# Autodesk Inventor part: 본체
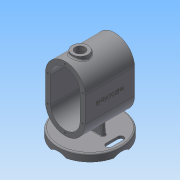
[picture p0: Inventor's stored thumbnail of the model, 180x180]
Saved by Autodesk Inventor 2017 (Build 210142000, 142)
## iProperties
Created: 2016-12
Part Number: 본체
Material: 알루미늄 6061
Document SubType Name: Modeling
Designer: mduedu
Density: 2.71 g/cm^3
Appearance: 기본값
Mass: 1098.85 g
Surface Area: 1080.89 cm^2
Volume: 405.481 cm^3
Author: mduedu
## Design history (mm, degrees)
sketch "스케치1"
  geometry: L1 (40, -25)-(40, 25); L2 (-40, 25)-(-40, -25); L3 (-40, -25)-(40, 25); L4 (40, -25)-(-40, 25); L5 (0, 25)-(0, -25); A1 r 40 centre (0, 25) between (40, 25) and (-40, 25); A2 r 40 centre (0, -25) between (-40, -25) and (40, -25); 1 further point
  constraints: 10 end point, 4 point on circle, 3 tangent, 2 centre point, 2 midpoint, 2 parallel, 1 vertical
  dimensions: "d0" = 130 dimension on A2 A1; "d2" = 80 distance between parallel lines of L1 L2
extrude "돌출1" new body sketch "스케치1" stored distance "d3" = 100; taper "d4" = 0 deg
feature "쉘1" dims "d5" = 10
sketch "스케치2"
  geometry: L1 (-75, 65)-(-90, 65); L2 (-90, 65)-(-90, 0); L3 (-75, 0)-(-75, 65); L4 (-75, 0)-(-90, 0); 1 further point
  constraints: 8 end point, 1 horizontal, 1 horizontal alignment, 1 parallel, 1 perpendicular
  dimensions: "d6" = 90 distance from line of L2 point (0, 0); "d83" = 15 distance of L1.start L1.end; "d84" = 130 diameter of L1 L4
revolve "회전1" sketch "스케치2" stored, may be unused: angle "d85" = 90 deg
fillet "모깎기5" dims "d86" = 3
hole "구멍6" diameter "d89" = 120; stored, may be unused: countersink angle "d93" = 90 deg, drill point angle "d95" = 0 deg; dims "d87" = 10, "d88" = 10, "d90" = 6, "d91" = 4, "d92" = 2, "d94" = 10
sketch "스케치15"
  geometry: L1 (-90, -60)-(-90, 60) reference; A1 r 21.75 centre (-105.75, 0) between (-90, -15) and (-90, 15); 3 further points
  constraints: 3 point on circle, 2 point on line, 1 centre point, 1 horizontal alignment, 1 midpoint
  dimensions: "d119" = 30 distance of A1.start A1.end; "d120" = 6 distance of point (-84, 0) point (-90, 0)
extrude "돌출6" cut sketch "스케치15" stored distance "d97" = 10; taper "d98" = 0 deg
sketch "스케치5"
  geometry: L1 (4, -30)-(-4, -30); L2 (-4, -30)-(-4, 30); L3 (-4, 30)-(4, 30); L4 (4, 30)-(4, -30); L5 (4, -30)-(-4, 30); L6 (-4, -30)-(4, 30); 3 further points
  constraints: 12 end point, 3 midpoint, 2 parallel, 1 coincident, 1 horizontal, 1 perpendicular
  dimensions: "d22" = 8 distance of L2.end L3.end; "d24" = 60 distance of L1.end L2.end
extrude "돌출3" join sketch "스케치5" stored distance "d25" = 80; taper "d26" = 0 deg
feature "면 기울기1" dims angle "d27" = 5 deg
sketch "스케치6"
  geometry: L1 (-28.115, -53.453)-(-30, -75); L2 (-62, -75)-(62, -75) reference; A1 r 40 centre (0, -25) between (-40, -25) and (40, -25) reference; 1 further point
  constraints: 2 end point, 1 point on circle, 1 point on line
  dimensions: "d28" = 30 horizontal distance of A1.centre L1.end; "d102" = 85 deg angle of L2 L1
feature "리브1" sketch "스케치6" dims "d30" = 1, "d31" = 8, "d32" = 0, "d33" = 0, "d34" = 1, "d35" = 1
fillet "모깎기2" dims "d36" = 3
fillet "모깎기3" dims "d37" = 1, "d38" = 1
node "작업 평면1"
sketch "스케치9"
  geometry: 1 further point
sketch "스케치7"
  geometry: L1 (40, 50)-(-40, 50) reference; C1 r 16 at (0, 20); 1 further point
  constraints: 1 centre point, 1 vertical alignment
  dimensions: "d40" = 32 diameter of C1; "d41" = 30 distance from line of C1.centre L1
extrude "돌출4" join sketch "스케치7" stored distance "d42" = 80; taper "d43" = 0 deg
hole "구멍2" diameter "d46" = 20; stored, may be unused: countersink angle "d50" = 90 deg, drill point angle "d52" = 118 deg; dims "d44" = 10, "d45" = 10, "d47" = 6, "d48" = 4, "d49" = 2, "d51" = 8
fillet "모깎기4" dims "d53" = 3
node "작업 평면2"
sketch "스케치8"
  geometry: C1 r 16 at (0, 0) reference; C2 r 15 at (0, 0); 1 further point
  constraints: 1 centre point, 1 coincident
  dimensions: "d55" = 30 diameter of C2
extrude "돌출5" cut sketch "스케치8" stored distance "d56" = 80; taper "d57" = 0 deg
chamfer "모따기1" distance "d58" = 1; stored, may be unused: second distance "d59" = 2, angle "d60" = 45 deg
sketch "스케치10"
  geometry: 2 further points
  constraints: 1 coincident, 1 other
feature "엠보싱1" sketch "스케치10" dims "d0" = 130, "d2" = 80, "d61" = 0.5, "d62" = 0
sketch "스케치11"
  geometry: 1 further point
hole "구멍3" sketch "스케치11" at (0, 60) diameter "d63" = 3.242; stored, may be unused: countersink angle "d67" = 90 deg, drill point angle "d69" = 120 deg; dims "d64" = 8.6, "d65" = 4, "d66" = 2, "d68" = 10.6
sketch "스케치12"
  geometry: 1 further point
hole "구멍5" sketch "스케치12" at (0, 60) diameter "d70" = 3.242; stored, may be unused: countersink angle "d74" = 90 deg, drill point angle "d76" = 120 deg; dims "d71" = 8.6, "d72" = 4, "d73" = 2, "d75" = 10.6
sketch "스케치16"
  geometry: L1 (0, 0)-(0, 50); L2 (-56, 12)-(-56, -12); L3 (-44, 12)-(-44, -12); L4 (-50, -12)-(-50, 12); A1 r 50 centre (0, 0) between (0, 50) and (-50, 0); A2 r 6 centre (-50, 12) between (-44, 12) and (-56, 12); A3 r 6 centre (-50, -12) between (-56, -12) and (-44, -12); 1 further point
  constraints: 8 end point, 6 point on circle, 4 tangent, 3 centre point, 3 parallel, 1 coincident, 1 equal radius, 1 horizontal alignment, 1 midpoint, 1 vertical
  dimensions: "d103" = 100 diameter of A1; "d121" = 6 radius of A2; "d122" = 24 distance of L4.start L4.end
extrude "돌출7" cut sketch "스케치16" stored distance "d123" = 10; taper "d124" = 0 deg
node "솔리드1"
pattern_circular "원형 패턴1" dims angle "d100" = 90 deg
mirror "대칭1"
pattern_linear "직사각형 패턴1"
pattern_linear "직사각형 패턴2"
mirror "대칭2"
sketch "스케치13"
  geometry: L1 (-40, 25)-(-40, -25) reference; L2 (40, -25)-(40, 25) reference; L3 (35, 25)-(35, -25); L4 (-35, -25)-(-35, 25); A1 r 40 centre (0, 25) between (40, 25) and (-40, 25) reference; A2 r 40 centre (0, -25) between (-40, -25) and (40, -25) reference; A3 r 35 centre (0, 25) between (35, 25) and (-35, 25); A4 r 35 centre (0, -25) between (-35, -25) and (35, -25); 2 further points
  constraints: 5 point on circle, 4 end point, 2 centre point, 3 other
  dimensions: "d77" = 5 distance between parallel lines of L3 L2
sketch "스케치14"
  geometry: L1 (-40, 25)-(-40, -25) reference; L2 (40, -25)-(40, 25) reference; L3 (35, 25)-(35, -25); L4 (-35, -25)-(-35, 25); A1 r 40 centre (0, 25) between (40, 25) and (-40, 25) reference; A2 r 40 centre (0, -25) between (-40, -25) and (40, -25) reference; A3 r 35 centre (0, 25) between (35, 25) and (-35, 25); A4 r 35 centre (0, -25) between (-35, -25) and (35, -25); 2 further points
  constraints: 5 point on circle, 4 end point, 2 centre point, 3 other
  dimensions: "d80" = 5 distance between parallel lines of L2 L3
